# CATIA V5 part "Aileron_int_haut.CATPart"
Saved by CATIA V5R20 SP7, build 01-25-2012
Part number: Aileron_int_haut
Bounding box of the stored display mesh (mm): x -250 to 250, y -9.796 to 88.072, z 0 to 129.099
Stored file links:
  F:\Travaux\Modélisations\CFAO_2011\MMS\MMS_GR2\AA_OK\tquattrone\Catia\Aileron_int_haut.CATPart
  C:\Users\Tom\Documents\Cours 2A\CFAO\Projet thinkmotion\Aileron_citroen.CATProduct
  F:\Travaux\Modélisations\CFAO_2011\MMS\MMS_GR2\AA_OK\tquattrone\Catia\Bielle 3.CATPart
  F:\Travaux\Modélisations\CFAO_2011\MMS\MMS_GR2\AA_OK\tquattrone\Catia\Tige_verin.CATPart
  F:\Travaux\Modélisations\CFAO_2011\MMS\MMS_GR2\AA_OK\tquattrone\Catia\Corps_verin.CATPart
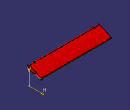
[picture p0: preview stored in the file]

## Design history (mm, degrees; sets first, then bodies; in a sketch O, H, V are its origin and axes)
Parameters
  Epaisseur_trou_bielle3 = 5 mm
External parameters (linked from other documents)
  `External.Diamètre_trou_bielle3` = 6 mm
  External.Diametre_trou_tige = 14 mm
  External.epaisseur_corps_verin = 3 mm
  External.Rayon_tige_verin = 10.75 mm
  External.Epaisseur_bielle_3 = 5 mm
Set1
  Plane1 "Plan_bout": linked copy from another document
  Plane2 "Plan_sym": linked copy from another document
  Plane3 "Plan_bielle2/3": linked copy from another document
  Plane4 "Plan_verin": linked copy from another document
  Point1 "Point_bielle_32": linked copy from another document
  Point2 "Point_centre_tige_verin": linked copy from another document
  Plane5 "Plan_bielle1": linked copy from another document
Body1 (main body)
  Sketch1 on Plane1, origin (250, 0, 0), H (0, 1, 0), V (0, 0, 1)
    spline S1 through (2.536, 128.3322) (25.0007, 119.4727) (57.8897, 104.9648) (84.7612, 90.6872)
    spline S2 through (84.7612, 90.6872) (87.6227, 88.9761) (87.9285, 88.4326) (87.7615, 87.0291) (87.68, 86.9712)
    spline S3 through (87.68, 86.9712) (76.5637, 87.4899) (61.0517, 89.5143) (40.2505, 95.4423)
    spline S4 through (40.2505, 95.4423) (35.2019, 93.6975) (28.3848, 93.1299) (15.9829, 95.9879) (5.95, 102.401) (-1.5051, 109.7203) (-7.497, 116.4819)
    spline S5 through (-7.497, 116.4819) (-9.7962, 121.5706) (-8.7511, 125.2651) (-6.3914, 127.6999) (2.536, 128.3322)
    point P1 (12.3735, 124.5294)
    point P2 (84.7612, 90.6872)
    point P3 (84.7612, 90.6872)
    point P4 (87.68, 86.9712)
    point P5 (87.68, 86.9712)
    point P6 (40.2505, 95.4423)
    point P7 (40.2505, 95.4423)
    point P8 (-7.497, 116.4819)
    point P9 (-7.497, 116.4819)
    point P10 (2.536, 128.3322)
    point P11 (2.536, 128.3322)
    coincidence: P2 P3, P4 P5, P6 P7, P8 P9, P10 P11, P1 S1
  Pad1: profile Sketch1, direction (1, 0, 0), up to Plane2
  Sketch2 on Plane3, origin (210, 0, 0), H (0, 1, 0), V (0, 0, 1)
    spline S1 through (-10.7505, 119.3982) (-6.877, 114.5755) (0.5682, 105.8788) (17.0525, 94.5958)
    spline S2 through (17.0525, 94.5958) (11.4575, 112.8531) (10.3215, 119.4806) (8.8069, 123.5263) (6.7123, 125.4473) (1.8249, 127.3683) (-3.4989, 127.019) (-7.4795, 125.0821) (-10.7505, 119.3982)
    point P1 (17.0525, 94.5958)
    point P2 (17.0525, 94.5958)
    point P3 (-10.7505, 119.3982)
    point P4 (-10.7505, 119.3982)
    coincidence: P1 P2, P3 P4
  Pocket1: profile Sketch2, direction (1, 0, 0), length 5
  Sketch3 on Plane4, origin (180, 0, 0), H (0, 1, 0), V (0, 0, 1)
    line L1 (7.1154, 98.6113) -> (18.047, 118.6239)
    line L2 (18.047, 118.6239) -> (46.7526, 107.4967)
    line L3 (46.7526, 107.4967) -> (41.5378, 87.3961)
    line L4 (41.5378, 87.3961) -> (7.1154, 98.6113)
  Pocket2: profile Sketch3, direction (-1, 0, 0), length 10.75 {= External.Rayon_tige_verin}, mirrored extent
  Sketch4 on Plane4, origin (180, 0, 0), H (0, 1, 0), V (0, 0, 1)
    circle A1 centre (27.5, 102.496) radius 7
    point P1 (27.5, 102.496)
    reference projected point E1 (27.5, 102.496) from Point2
    radius A1 = 7 {= External.Diametre_trou_tige /2}
    coincidence: P1 E1
  Pad2: profile Sketch4, direction (1, 0, 0), length 10.75 {= External.Rayon_tige_verin}, mirrored extent
  Sketch5 on Plane3, origin (210, 0, 0), H (0, 1, 0), V (0, 0, 1)
    circle A1 centre (0, 118) radius 3
    point P1 (0, 118)
    reference projected point E1 (0, 118) from Point1
    radius A1 = 3 {= `External.Diamètre_trou_bielle3` /2}
    coincidence: P1 E1
  Pad3: profile Sketch5, direction (1, 0, 0), length 5 {= External.Epaisseur_bielle_3}
  Mirror1: of the body so far, about Plane2
  Sketch6 on start face of Pad1, origin (250, 0, 0), H (0, 1, 0), V (0, 0, 1)
    spline S1 through (40.1935, 94.2036) (52.6437, 90.128) (61.4951, 88.1707) (70.7782, 86.8016) (80.3377, 85.9923) (88.0715, 85.7947)
    reference projected curve E1 from edge [face of Pad1 | start face of Pad1]
    reference projected curve E2 from edge [face of Pad1 | start face of Pad1]
    reference projected curve E3 from edge [face of Pad1 | start face of Pad1]
    reference projected curve E4 from edge [face of Pad1 | start face of Pad1]
    reference projected point E5 (87.68, 86.9712) from vertex [face of Pad1 | start face of Pad1 | face of Pad1]
    reference projected point E6 (40.2505, 95.4423) from vertex [face of Pad1 from Sketch1.S4 | face of Pad1 from Sketch1.S3 | start face of Pad1]
    point P1 (40.1935, 94.2036)
    point P2 (52.6437, 90.128)
    point P3 (61.4951, 88.1707)
    point P4 (70.7782, 86.8016)
    point P5 (80.3377, 85.9923)
    point P6 (88.0715, 85.7947)
    distance P2 E1 = 1.24
    distance P3 E2 = 1.24
    distance P4 E3 = 1.24
    distance P5 E4 = 1.24
    distance P6 E5 = 1.24
    distance P1 E6 = 1.24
